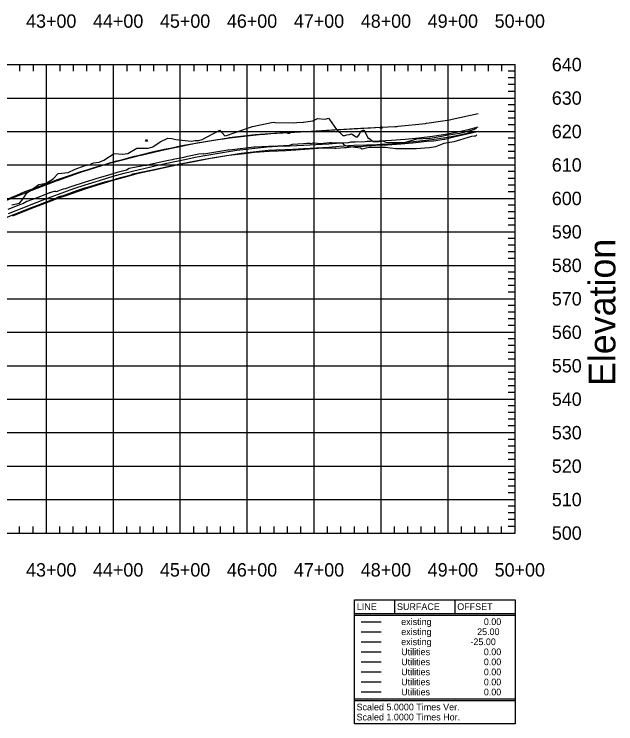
# Model space of a CAD drawing. Extents: x 704797 to 712284, y 374940 to 376945.
# Drawn here: x 711386 to 712284, y 374940 to 376001 of the extents above; entities that cross this region are included whole.
import ezdxf

# ---------------------------------------------------------------- set-up
doc = ezdxf.new("R2010")
doc.units = 0
for name, color, linetype in [('1', 7, 'Continuous'), ('10', 7, 'Continuous'), ('12', 7, 'Continuous'), ('13', 7, 'Continuous'), ('48', 7, 'Continuous'), ('61', 7, 'Continuous'), ('63', 7, 'Continuous'), ('Default_Profile', 7, 'Continuous'), ('Existing', 7, 'Continuous')]:
    doc.layers.add(name, color=color, linetype=linetype)

msp = doc.modelspace()

# ---------------------------------------------------------------- linework, layer by layer
for points in [[(711933.7, 375833.5), (711935.2, 375830.5), (711932.2, 375830.5)], [(711795.6, 375825.7), (711797.1, 375822.7), (711794.1, 375822.7)], [(711583.1, 375813.8), (711584.6, 375810.8), (711581.6, 375810.8)]]:
    msp.add_lwpolyline(points, close=True)
at = {"layer": '10'}
for points in [[(711382.1, 375715.8), (711393.6, 375718.6), (711398.8, 375725.1), (711404.5, 375733.6), (711405.1, 375733.9), (711405.5, 375734.2), (711422.3, 375746.3), (711433.2, 375748.4), (711443.7, 375755), (711451.3, 375762.5), (711466.2, 375764.4), (711476.8, 375769.4), (711490, 375774.3), (711499, 375776.4), (711500.5, 375777.1), (711503.9, 375778.9), (711512.6, 375779.6), (711519.6, 375782.5), (711534.7, 375792.6), (711547.4, 375791.6), (711555.3, 375792.4), (711568.9, 375800.5), (711585.7, 375800.4), (711592.4, 375802.5), (711603.6, 375809.9), (711615.3, 375815.6), (711621, 375815.1), (711627.2, 375813.3), (711649.8, 375811), (711656.1, 375812), (711661.6, 375812), (711662.8, 375812.3), (711666.1, 375813.4), (711692.7, 375827.6), (711700.3, 375819.2), (711702.9, 375819.3), (711737.3, 375831.3), (711741.6, 375832.9), (711772.5, 375839.3), (711775.4, 375838.9), (711802.2, 375838.5), (711807.6, 375839), (711817.1, 375839.5), (711817.9, 375839.6), (711831.7, 375841.6), (711838.5, 375845), (711850.3, 375844), (711855.1, 375845.2), (711856.7, 375843.5), (711866.9, 375828.6), (711867.6, 375828.1), (711876.3, 375819.6), (711879.7, 375819.4), (711882.5, 375820.6), (711886.5, 375820.9), (711889.3, 375821.9), (711896.6, 375817.7), (711898.6, 375817.5), (711898.9, 375817.9), (711901.5, 375821.3), (711903.6, 375826.2), (711908.1, 375828.2), (711913.6, 375816.3), (711913.9, 375815.3), (711915.3, 375815.5), (711921.8, 375810.5), (711930.2, 375810.5), (711935.7, 375811.5), (711940.5, 375809.6), (711950.9, 375809.3), (711962, 375809.3), (711964, 375809.3), (711968.4, 375809.3), (711986.9, 375814.4), (712005.1, 375815.4), (712007.6, 375815.5), (712026.4, 375819), (712030.9, 375820), (712051.4, 375822.8), (712055.9, 375824.1), (712072, 375828.6), (712074.5, 375829.8), (712076.8, 375831.1)], [(712076.9, 375820.5), (712074.6, 375818.7), (712073.1, 375818.4), (712068.8, 375817.9), (712052.1, 375813.2), (712042.4, 375810.2), (712027.2, 375807.4), (712014.9, 375802.8), (712005.9, 375801.3), (711999, 375800.6), (711985.9, 375799.7), (711975.8, 375799.8), (711955.9, 375799.8), (711947.1, 375800.7), (711940.3, 375801.5), (711932.2, 375801.8), (711915.7, 375801.6), (711911.1, 375800.8), (711909.3, 375799.9), (711905.2, 375799.2), (711902.8, 375800.4), (711883.6, 375803), (711879, 375805), (711876.3, 375808.1), (711861.7, 375808.1), (711859.5, 375808.4), (711857.3, 375808.7), (711847.7, 375807.4), (711845.1, 375807.3), (711838.8, 375807.5), (711832.4, 375808.2), (711831.9, 375808.2), (711829.4, 375807.2), (711828.2, 375807.4), (711826.6, 375807.4), (711822.5, 375807.6), (711817.9, 375807.3), (711801, 375806), (711799.3, 375805.4), (711799.1, 375805.4), (711797.2, 375804.8), (711796.7, 375804.7), (711796.1, 375804.5), (711779.3, 375803.7), (711777.8, 375803.3), (711775.9, 375803.7), (711745.2, 375802.1), (711743.7, 375801.9), (711711.2, 375798.3), (711707.1, 375797.7), (711706.2, 375798.1), (711704.8, 375797.4), (711668.9, 375791.5), (711667.6, 375792.3), (711661.3, 375791.4), (711644.6, 375788), (711640.3, 375787.1), (711639, 375786.7), (711633.8, 375785.5), (711622.8, 375783.7), (711621.3, 375783.4), (711616.1, 375782.3), (711602.3, 375779.2), (711588.8, 375776.2), (711583.1, 375774.9), (711581.9, 375774.6), (711578.4, 375774.4), (711557.3, 375770.1), (711553.5, 375767.9), (711547.1, 375766.2), (711539.3, 375764.1), (711529.7, 375761.4), (711507.4, 375754.8), (711501.4, 375753), (711491.5, 375750), (711470.3, 375742.7), (711463.4, 375740.3), (711463, 375740.1), (711462.4, 375740), (711461.9, 375739.9), (711458.5, 375739.1), (711455.5, 375738.3), (711450.7, 375736.1), (711449.7, 375735.9), (711448, 375735.5), (711447.9, 375735.6), (711447.7, 375736), (711446.6, 375735.9), (711445.4, 375735.7), (711443.4, 375735.1), (711440.4, 375734.1), (711439.1, 375733.8), (711438.3, 375733.6), (711437.8, 375733.6), (711437.4, 375733.5), (711418.4, 375726), (711404.6, 375720.7), (711398.3, 375717.6), (711395.1, 375716.3), (711376, 375708.7)]]:
    msp.add_lwpolyline(points, dxfattribs=at)
at = {"layer": '12'}
for points in [[(711377, 375703.2), (711402.2, 375713), (711413.6, 375717.6), (711435.5, 375726), (711451.7, 375732), (711474.7, 375740.1), (711491.5, 375745.9), (711513.2, 375752.4), (711515.8, 375753.2), (711533.2, 375758.6), (711549.7, 375763), (711572.6, 375768.9), (711589.8, 375772.7), (711611.3, 375777.6), (711630.4, 375781.5), (711640.6, 375783.7), (711655.9, 375786.9), (711673.4, 375790.1), (711699.9, 375794.5), (711718.2, 375797.5), (711740.6, 375800.3), (711758.9, 375802.2), (711763.6, 375802.4), (711779.1, 375803.4), (711797.5, 375803.9), (711818.2, 375805), (711836.3, 375806), (711855.4, 375807.1), (711855.6, 375807.2), (711872.6, 375808.7), (711884.7, 375809.3), (711888.4, 375809.9), (711894.9, 375810), (711909.7, 375810.7), (711912.8, 375810.8), (711917.9, 375811), (711931, 375811.4), (711949, 375812.4), (711969.8, 375814), (711989.9, 375816.1), (712010.2, 375818.4), (712029.8, 375821.5), (712046.1, 375824.6), (712065.9, 375829.1), (712075.3, 375831.7), (712078.6, 375832.5)], [(711383.6, 375699.7), (711391.2, 375702.7), (711414.6, 375712), (711421.4, 375714.6), (711453.5, 375726.7), (711461.6, 375729.5), (711493.3, 375740.5), (711502.3, 375743.2), (711533.2, 375752.8), (711561, 375760.3), (711571.4, 375763), (711599.3, 375769.3), (711610.1, 375771.7), (711640.2, 375778), (711654, 375780.9), (711681.2, 375785.9), (711696.5, 375788.5), (711724.5, 375793.1), (711738.1, 375794.8), (711765.1, 375797.6), (711776.3, 375798.3), (711777.7, 375798.3), (711801.6, 375799), (711817.7, 375799.9), (711837.1, 375801.1), (711855.6, 375802.1), (711855.8, 375802.3), (711871.2, 375803.7), (711885, 375804.4), (711888.1, 375804.8), (711893.1, 375804.9), (711911.6, 375805.8), (711913.9, 375805.8), (711927.3, 375806.3), (711951.1, 375807.6), (711967.7, 375808.9), (711991.3, 375811.3), (712009.5, 375813.4), (712029.9, 375816.5), (712046.4, 375819.6), (712064.6, 375823.7), (712069.2, 375825)]]:
    msp.add_lwpolyline(points, dxfattribs=at)
at = {"layer": '13'}
msp.add_lwpolyline([(712078.6, 375825.5), (712077, 375825.1), (712062.3, 375821.7), (712046.3, 375818.1), (712028.7, 375813.4), (712027.2, 375813.3), (712012.2, 375811), (712010.6, 375810.9), (712002.2, 375810.5), (711980.4, 375808.1), (711963.1, 375806.4), (711943, 375805.3), (711925.2, 375804.4), (711907, 375803.2), (711892.9, 375802.5), (711881.4, 375801.2), (711879, 375800.9), (711866.5, 375800.3), (711865.3, 375800.1), (711864, 375800.4), (711863.8, 375800.3), (711859.7, 375800.8), (711859.4, 375800.8), (711853.6, 375800.8), (711840.1, 375800), (711826.4, 375799.1), (711806.3, 375797.7), (711791.9, 375796.8), (711779.8, 375796.3), (711766.5, 375795.5), (711744.5, 375794.1), (711729.6, 375792.2), (711706.3, 375789.8), (711682.5, 375785.8), (711681.6, 375785.7), (711664.3, 375782.9), (711633.5, 375776.6), (711615.2, 375772.8), (711596.6, 375768.7), (711580.3, 375765), (711579.5, 375764.8), (711577.1, 375764.7), (711562.9, 375761.8), (711560.4, 375760.3), (711542.5, 375755.7), (711530.9, 375752.5), (711522.6, 375750.1), (711517.2, 375748.6), (711496.6, 375742.4), (711490.6, 375740.6), (711478.8, 375736.6), (711457, 375728.9), (711456.7, 375728.8), (711456.4, 375728.8), (711456.1, 375728.7), (711452.4, 375727.8), (711448.1, 375726), (711447.2, 375725.5), (711446.2, 375725), (711445.1, 375724.5), (711426.4, 375717.4), (711424.5, 375716.6), (711407, 375709.9), (711387.1, 375702.1), (711365.5, 375693.4)], dxfattribs=at)
at = {"layer": '48'}
msp.add_line((711795.6, 375824.2), (711933.7, 375832), dxfattribs=at)
msp.add_lwpolyline([(711379.4, 375726.4), (711388.3, 375730), (711397.1, 375733.6), (711406, 375737.1), (711414.8, 375740.5), (711423.7, 375743.9), (711432.5, 375747.2), (711441.4, 375750.4), (711450.3, 375753.6), (711459.1, 375756.7), (711468, 375759.7), (711476.8, 375762.6), (711485.7, 375765.5), (711494.5, 375768.4), (711503.4, 375771.1), (711512.2, 375773.8), (711521.1, 375776.4), (711529.9, 375779), (711538.8, 375781.5), (711547.7, 375783.9), (711556.5, 375786.2), (711565.4, 375788.5), (711574.2, 375790.8), (711591.9, 375795), (711600.8, 375797), (711609.6, 375798.9), (711618.5, 375800.8), (711627.3, 375802.6), (711636.2, 375804.4), (711645, 375806.1), (711653.9, 375807.7), (711662.8, 375809.2), (711671.6, 375810.7), (711680.5, 375812.1), (711689.3, 375813.4), (711698.2, 375814.7), (711707, 375815.9), (711715.9, 375817), (711724.7, 375818.1), (711733.6, 375819.1), (711742.4, 375820.1), (711751.3, 375820.9), (711760.2, 375821.7), (711769, 375822.4), (711777.9, 375823.1), (711786.7, 375823.7), (711795.6, 375824.2)], dxfattribs=at)
at = {"layer": '61'}
for p, q in [((708133.7, 375925.5), (712133.7, 375925.5)), ((711393.7, 375925.5), (711393.7, 375915.5)), ((711413.7, 375925.5), (711413.7, 375915.5)), ((711433.7, 375225.5), (711433.7, 375925.5)), ((711453.7, 375925.5), (711453.7, 375915.5)), ((711473.7, 375925.5), (711473.7, 375915.5)), ((711493.7, 375925.5), (711493.7, 375915.5)), ((711513.7, 375925.5), (711513.7, 375915.5)), ((711533.7, 375225.5), (711533.7, 375925.5)), ((711553.7, 375925.5), (711553.7, 375915.5)), ((711573.7, 375925.5), (711573.7, 375915.5)), ((711593.7, 375925.5), (711593.7, 375915.5)), ((711613.7, 375925.5), (711613.7, 375915.5)), ((711633.7, 375225.5), (711633.7, 375925.5)), ((711653.7, 375925.5), (711653.7, 375915.5)), ((711673.7, 375925.5), (711673.7, 375915.5)), ((711693.7, 375925.5), (711693.7, 375915.5)), ((711713.7, 375925.5), (711713.7, 375915.5)), ((711733.7, 375225.5), (711733.7, 375925.5)), ((711753.7, 375925.5), (711753.7, 375915.5)), ((711773.7, 375925.5), (711773.7, 375915.5)), ((711793.7, 375925.5), (711793.7, 375915.5)), ((711813.7, 375925.5), (711813.7, 375915.5)), ((711833.7, 375225.5), (711833.7, 375925.5)), ((711853.7, 375925.5), (711853.7, 375915.5)), ((711873.7, 375925.5), (711873.7, 375915.5)), ((711893.7, 375925.5), (711893.7, 375915.5)), ((711913.7, 375925.5), (711913.7, 375915.5)), ((711933.7, 375225.5), (711933.7, 375925.5)), ((711953.7, 375925.5), (711953.7, 375915.5)), ((711973.7, 375925.5), (711973.7, 375915.5)), ((711993.7, 375925.5), (711993.7, 375915.5)), ((712013.7, 375925.5), (712013.7, 375915.5)), ((712033.7, 375225.5), (712033.7, 375925.5)), ((712053.7, 375925.5), (712053.7, 375915.5)), ((712073.7, 375925.5), (712073.7, 375915.5)), ((712093.7, 375925.5), (712093.7, 375915.5)), ((712113.7, 375925.5), (712113.7, 375915.5)), ((712133.7, 375225.5), (712133.7, 375925.5)), ((712133.7, 375915.5), (712123.7, 375915.5)), ((712133.7, 375905.5), (712123.7, 375905.5)), ((712133.7, 375895.5), (712123.7, 375895.5)), ((712133.7, 375885.5), (712123.7, 375885.5)), ((708133.7, 375875.5), (712133.7, 375875.5)), ((712133.7, 375865.5), (712123.7, 375865.5)), ((712133.7, 375855.5), (712123.7, 375855.5)), ((712133.7, 375845.5), (712123.7, 375845.5)), ((712133.7, 375835.5), (712123.7, 375835.5)), ((708133.7, 375825.5), (712133.7, 375825.5)), ((712133.7, 375815.5), (712123.7, 375815.5)), ((712133.7, 375805.5), (712123.7, 375805.5)), ((712133.7, 375795.5), (712123.7, 375795.5)), ((712133.7, 375785.5), (712123.7, 375785.5)), ((708133.7, 375775.5), (712133.7, 375775.5)), ((712133.7, 375765.5), (712123.7, 375765.5)), ((712133.7, 375755.5), (712123.7, 375755.5)), ((712133.7, 375745.5), (712123.7, 375745.5)), ((712133.7, 375735.5), (712123.7, 375735.5)), ((708133.7, 375725.5), (712133.7, 375725.5)), ((712133.7, 375715.5), (712123.7, 375715.5)), ((712133.7, 375705.5), (712123.7, 375705.5)), ((712133.7, 375695.5), (712123.7, 375695.5)), ((712133.7, 375685.5), (712123.7, 375685.5)), ((708133.7, 375675.5), (712133.7, 375675.5)), ((712133.7, 375665.5), (712123.7, 375665.5)), ((712133.7, 375655.5), (712123.7, 375655.5)), ((712133.7, 375645.5), (712123.7, 375645.5)), ((712133.7, 375635.5), (712123.7, 375635.5)), ((708133.7, 375625.5), (712133.7, 375625.5)), ((712133.7, 375615.5), (712123.7, 375615.5)), ((712133.7, 375605.5), (712123.7, 375605.5)), ((712133.7, 375595.5), (712123.7, 375595.5)), ((712133.7, 375585.5), (712123.7, 375585.5)), ((708133.7, 375575.5), (712133.7, 375575.5)), ((712133.7, 375565.5), (712123.7, 375565.5)), ((712133.7, 375555.5), (712123.7, 375555.5)), ((712133.7, 375545.5), (712123.7, 375545.5)), ((712133.7, 375535.5), (712123.7, 375535.5)), ((708133.7, 375525.5), (712133.7, 375525.5)), ((712133.7, 375515.5), (712123.7, 375515.5)), ((712133.7, 375505.5), (712123.7, 375505.5)), ((712133.7, 375495.5), (712123.7, 375495.5)), ((712133.7, 375485.5), (712123.7, 375485.5)), ((708133.7, 375475.5), (712133.7, 375475.5)), ((712133.7, 375465.5), (712123.7, 375465.5)), ((712133.7, 375455.5), (712123.7, 375455.5)), ((712133.7, 375445.5), (712123.7, 375445.5)), ((712133.7, 375435.5), (712123.7, 375435.5)), ((708133.7, 375425.5), (712133.7, 375425.5)), ((712133.7, 375415.5), (712123.7, 375415.5)), ((712133.7, 375405.5), (712123.7, 375405.5)), ((712133.7, 375395.5), (712123.7, 375395.5)), ((712133.7, 375385.5), (712123.7, 375385.5)), ((708133.7, 375375.5), (712133.7, 375375.5)), ((712133.7, 375365.5), (712123.7, 375365.5)), ((712133.7, 375355.5), (712123.7, 375355.5)), ((712133.7, 375345.5), (712123.7, 375345.5)), ((712133.7, 375335.5), (712123.7, 375335.5)), ((708133.7, 375325.5), (712133.7, 375325.5)), ((712133.7, 375315.5), (712123.7, 375315.5)), ((712133.7, 375305.5), (712123.7, 375305.5)), ((712133.7, 375295.5), (712123.7, 375295.5)), ((712133.7, 375285.5), (712123.7, 375285.5)), ((708133.7, 375275.5), (712133.7, 375275.5)), ((712133.7, 375265.5), (712123.7, 375265.5)), ((712133.7, 375255.5), (712123.7, 375255.5)), ((712133.7, 375245.5), (712123.7, 375245.5)), ((711393.7, 375225.5), (711393.7, 375235.5)), ((711413.7, 375225.5), (711413.7, 375235.5)), ((711453.7, 375225.5), (711453.7, 375235.5)), ((711473.7, 375225.5), (711473.7, 375235.5)), ((711493.7, 375225.5), (711493.7, 375235.5)), ((711513.7, 375225.5), (711513.7, 375235.5)), ((711553.7, 375225.5), (711553.7, 375235.5)), ((711573.7, 375225.5), (711573.7, 375235.5)), ((711593.7, 375225.5), (711593.7, 375235.5)), ((711613.7, 375225.5), (711613.7, 375235.5)), ((711653.7, 375225.5), (711653.7, 375235.5)), ((711673.7, 375225.5), (711673.7, 375235.5)), ((711693.7, 375225.5), (711693.7, 375235.5)), ((711713.7, 375225.5), (711713.7, 375235.5)), ((711753.7, 375225.5), (711753.7, 375235.5)), ((711773.7, 375225.5), (711773.7, 375235.5)), ((711793.7, 375225.5), (711793.7, 375235.5)), ((711813.7, 375225.5), (711813.7, 375235.5)), ((711853.7, 375225.5), (711853.7, 375235.5)), ((711873.7, 375225.5), (711873.7, 375235.5)), ((711893.7, 375225.5), (711893.7, 375235.5)), ((711913.7, 375225.5), (711913.7, 375235.5)), ((711953.7, 375225.5), (711953.7, 375235.5)), ((711973.7, 375225.5), (711973.7, 375235.5)), ((711993.7, 375225.5), (711993.7, 375235.5)), ((712013.7, 375225.5), (712013.7, 375235.5)), ((712053.7, 375225.5), (712053.7, 375235.5)), ((712073.7, 375225.5), (712073.7, 375235.5)), ((712093.7, 375225.5), (712093.7, 375235.5)), ((712113.7, 375225.5), (712113.7, 375235.5)), ((712133.7, 375235.5), (712123.7, 375235.5)), ((708133.7, 375225.5), (712133.7, 375225.5)), ((711953.7, 375125.5), (711953.7, 375105.5)), ((712043.7, 375125.5), (712043.7, 375105.5)), ((711893.7, 375105.5), (712133.7, 375105.5)), ((711893.7, 375103), (712133.7, 375103)), ((711893.7, 374978), (712133.7, 374978)), ((711893.7, 374975.5), (712133.7, 374975.5))]:
    msp.add_line(p, q, dxfattribs=at)
msp.add_lwpolyline([(711893.7, 375125.5), (712133.7, 375125.5), (712133.7, 374940.5), (711893.7, 374940.5)], close=True, dxfattribs=at)
at = {"layer": '63'}
for p, q in [((711903.7, 375078), (711933.7, 375078)), ((711903.7, 375063), (711933.7, 375063))]:
    msp.add_line(p, q, dxfattribs=at)
at = {"layer": 'Default_Profile'}
for p, q in [((711903.7, 375048), (711933.7, 375048)), ((711903.7, 375033), (711933.7, 375033)), ((711903.7, 375018), (711933.7, 375018)), ((711903.7, 375003), (711933.7, 375003)), ((711903.7, 374988), (711933.7, 374988))]:
    msp.add_line(p, q, dxfattribs=at)
at = {"layer": 'Existing'}
msp.add_line((711903.7, 375093), (711933.7, 375093), dxfattribs=at)
msp.add_lwpolyline([(711373.3, 375722.5), (711412.4, 375738), (711413.3, 375738.3), (711449.6, 375752.2), (711449.6, 375752.2), (711449.7, 375752.3), (711449.7, 375752.3), (711449.9, 375752.4), (711450.1, 375752.4), (711450.1, 375752.4), (711450.1, 375752.4), (711450.1, 375752.4), (711489.1, 375766.3), (711489.5, 375766.4), (711489.7, 375766.4), (711516.4, 375774.6), (711532.9, 375779.5), (711533.3, 375779.6), (711533.7, 375779.7), (711574.4, 375790.2), (711575, 375790.3), (711613.3, 375799), (711613.7, 375799.1), (711659.1, 375808.6), (711705.8, 375816.2), (711706.2, 375816.2), (711706.6, 375816.3), (711745.5, 375821.2), (711745.6, 375821.2), (711782.5, 375823.5), (711782.9, 375823.5), (711820.4, 375825.7), (711821.2, 375825.7), (711821.2, 375825.7), (711859.8, 375827.9), (711860.3, 375828.2), (711860.3, 375828.2), (711886.6, 375829.5), (711886.6, 375829.5), (711886.6, 375829.5), (711893.2, 375829.8), (711903.4, 375830.3), (711913.6, 375830.9), (711916.6, 375831), (711916.7, 375831), (711917.7, 375831.1), (711923.8, 375831.4), (711934, 375831.9), (711944.2, 375832.5), (711954.4, 375833), (711957.7, 375833.2), (711959.2, 375833.3), (711964.6, 375833.9), (711974.8, 375834.9), (711985, 375836), (711995.2, 375837), (712000.1, 375837.5), (712001.4, 375837.7), (712005.4, 375838.3), (712015.6, 375839.9), (712025.8, 375841.5), (712036, 375843.1), (712039.6, 375843.7), (712078.6, 375852.5)], dxfattribs=at)

# ---------------------------------------------------------------- texts
at = {"layer": '1'}
for s, p in [(' LINE ', (711893.7, 375110.5)), (' SURFACE ', (711953.7, 375110.5)), (' OFFSET ', (712043.7, 375110.5)), ('existing', (711963.7, 375088)), ('0.00', (712087.1, 375088)), ('existing', (711963.7, 375073)), ('25.00', (712077.1, 375073)), ('existing', (711963.7, 375058)), ('-25.00', (712067.1, 375058)), ('Utilities', (711963.7, 375043)), ('0.00', (712087.1, 375043)), ('Utilities', (711963.7, 375028)), ('0.00', (712087.1, 375028)), ('Utilities', (711963.7, 375013)), ('0.00', (712087.1, 375013)), ('Utilities', (711963.7, 374998)), ('0.00', (712087.1, 374998)), ('Utilities', (711963.7, 374983)), ('0.00', (712087.1, 374983)), ('Scaled 5.0000 Times Ver.', (711897, 374960.5)), ('Scaled 1.0000 Times Hor.', (711897, 374945.5))]:
    msp.add_text(s, height=10, dxfattribs=at).set_placement(p)
at = {"layer": '61'}
for s, p in [('43+00', (711403.3, 375980.5)), ('44+00', (711503.3, 375980.5)), ('45+00', (711603.3, 375980.5)), ('46+00', (711703.3, 375980.5)), ('47+00', (711803.3, 375980.5)), ('48+00', (711903.3, 375980.5)), ('49+00', (712003.3, 375980.5)), ('50+00', (712103.3, 375980.5)), ('640', (712188.7, 375915.5)), ('640', (712188.7, 375915.5)), ('630', (712188.7, 375865.5)), ('620', (712188.7, 375815.5)), ('610', (712188.7, 375765.5)), ('600', (712188.7, 375715.5)), ('590', (712188.7, 375665.5)), ('580', (712188.7, 375615.5)), ('570', (712188.7, 375565.5)), ('560', (712188.7, 375515.5)), ('550', (712188.7, 375465.5)), ('540', (712188.7, 375415.5)), ('530', (712188.7, 375365.5)), ('520', (712188.7, 375315.5)), ('510', (712188.7, 375265.5)), ('500', (712188.7, 375215.5)), ('43+00', (711403.3, 375160.5)), ('44+00', (711503.3, 375160.5)), ('45+00', (711603.3, 375160.5)), ('46+00', (711703.3, 375160.5)), ('47+00', (711803.3, 375160.5)), ('48+00', (711903.3, 375160.5)), ('49+00', (712003.3, 375160.5)), ('50+00', (712103.3, 375160.5))]:
    msp.add_text(s, height=20, dxfattribs=at).set_placement(p)
msp.add_text('Elevation', height=40, rotation=90, dxfattribs=at).set_placement((712283.7, 375445.2))

doc.saveas('drawing.dxf')
